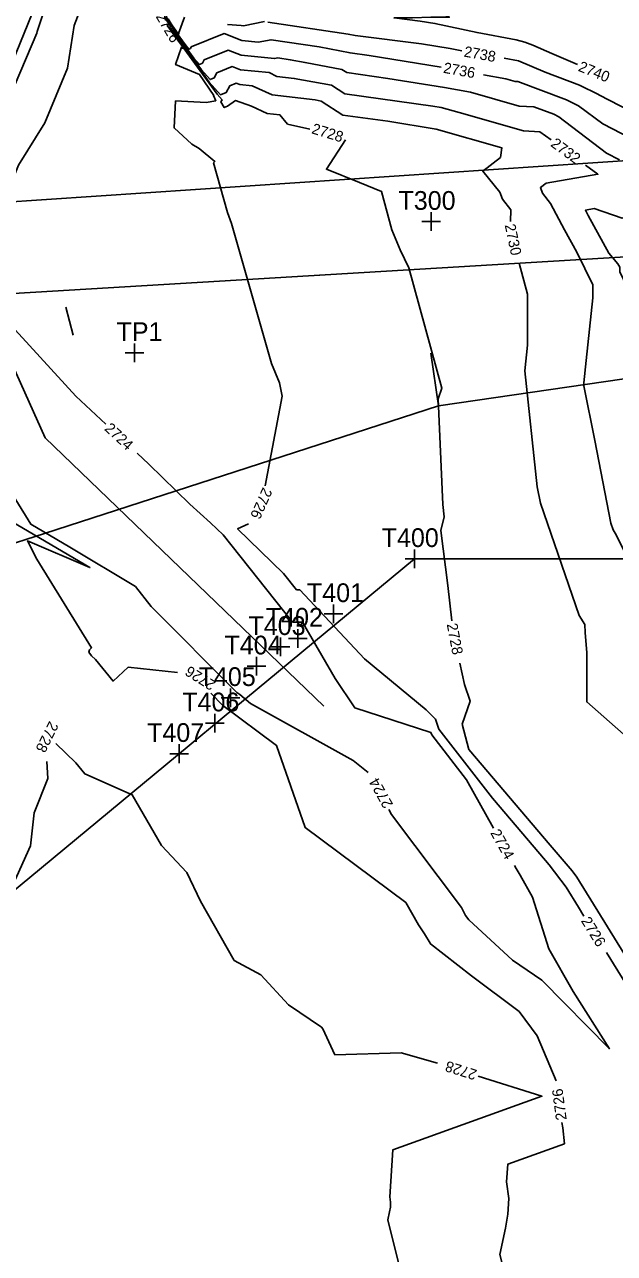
# Model space of a CAD drawing. Extents: x 1326424 to 1329294, y 1001359 to 1003823.
# Drawn here: x 1327879.6 to 1327989.8, y 1002856.6 to 1003086.3 of the extents above; entities that cross this region are included whole.
import ezdxf

# ---------------------------------------------------------------- set-up
doc = ezdxf.new("R2010")
doc.units = 0
for name, color, linetype in [('Default', 7, 'Continuous'), ('Prop Rem of Exist Asph Pvmt', 7, 'Continuous'), ('Prop SS Fill Line', 7, 'Continuous'), ('Prop SS Transition Line', 7, 'Continuous'), ('Scratch_Level_3', 7, 'Continuous')]:
    doc.layers.add(name, color=color, linetype=linetype)

msp = doc.modelspace()

# ---------------------------------------------------------------- linework, layer by layer
at = {"layer": 'Default'}
for p, q in [((1327659.26, 1003038.5), (1328184.23, 1003073.75)), ((1327956.95, 1003015.01), (1328177.22, 1003047.25)), ((1327956.95, 1003015.01), (1327955.51, 1003024.88)), ((1327883.39, 1002991.15), (1327956.95, 1003015.01)), ((1327655.18, 1002918.25), (1327883.39, 1002991.15))]:
    msp.add_line(p, q, dxfattribs=at)
msp.add_lwpolyline([(1327540.87, 1003325.42), (1327608.11, 1003285.07), (1327679.55, 1003254.32), (1327752.48, 1003225.71), (1327814.31, 1003211.74), (1327864.59, 1003173.14), (1327893.21, 1003143.63), (1327892.36, 1003116.11), (1327865.26, 1003049.62), (1327883.47, 1003009.08), (1327935.56, 1002958.9)], dxfattribs=at)
at = {"layer": 'Prop Rem of Exist Asph Pvmt'}
for p, q in [((1327955.6, 1003051.21), (1327955.6, 1003047.71)), ((1327957.35, 1003049.46), (1327953.85, 1003049.46)), ((1327901.93, 1003024.96), (1327898.43, 1003024.96)), ((1327900.18, 1003026.71), (1327900.18, 1003023.21)), ((1327952.45, 1002988.2), (1327952.45, 1002984.7)), ((1327954.2, 1002986.45), (1327950.7, 1002986.45)), ((1327937.36, 1002977.91), (1327937.36, 1002974.41)), ((1327939.11, 1002976.16), (1327935.61, 1002976.16)), ((1327930.68, 1002973.32), (1327930.68, 1002969.82)), ((1327929.2, 1002970.01), (1327925.7, 1002970.01)), ((1327927.45, 1002971.76), (1327927.45, 1002968.26)), ((1327932.43, 1002971.57), (1327928.93, 1002971.57)), ((1327922.96, 1002968.13), (1327922.96, 1002964.63)), ((1327924.71, 1002966.38), (1327921.21, 1002966.38)), ((1327918.13, 1002962.23), (1327918.13, 1002958.73)), ((1327919.88, 1002960.48), (1327916.38, 1002960.48)), ((1327915.16, 1002957.49), (1327915.16, 1002953.99)), ((1327916.91, 1002955.74), (1327913.41, 1002955.74)), ((1327908.5, 1002951.78), (1327908.5, 1002948.28)), ((1327910.25, 1002950.03), (1327906.75, 1002950.03))]:
    msp.add_line(p, q, dxfattribs=at)
msp.add_lwpolyline([(1327946.9, 1003116.73), (1327945.7, 1003116.52), (1327937.47, 1003113.03), (1327931.2, 1003110.86), (1327935.49, 1003103.61), (1327936.34, 1003101.4), (1327937.35, 1003100.59), (1327939.02, 1003099.75), (1327943.09, 1003097.24), (1327953.42, 1003090.51), (1327955.67, 1003089.46), (1327957.33, 1003088.47), (1327958.98, 1003087.65), (1327955.51, 1003087.68), (1327952.11, 1003087.53), (1327948.65, 1003087.52), (1327953.52, 1003086.91), (1327956.29, 1003086.49), (1327964.15, 1003084.78), (1327971.49, 1003083.44), (1327973.08, 1003082.98), (1327974.56, 1003082.42), (1327978.13, 1003080.88), (1327982.91, 1003078.81)], dxfattribs=at)
at = {"layer": 'Prop SS Fill Line'}
msp.add_line((1327888.69, 1003028.26), (1327887.37, 1003033.46), dxfattribs=at)
at = {"layer": 'Prop SS Transition Line'}
for p, q in [((1327872.68, 1003035.75), (1328093.84, 1003048.97)), ((1327952.45, 1002986.45), (1327671.95, 1002754.06)), ((1327952.45, 1002986.45), (1328127.23, 1002986.45))]:
    msp.add_line(p, q, dxfattribs=at)
at = {"layer": 'Scratch_Level_3'}
for points in [[(1327872.03, 1003054.66), (1327873.31, 1003056.72), (1327874.7, 1003061.52), (1327875.79, 1003070.18), (1327881.91, 1003084.69), (1327882, 1003084.98), (1327889.68, 1003108.17), (1327890.96, 1003110.45), (1327897.72, 1003115.14), (1327900.89, 1003116.1), (1327905.83, 1003122.65), (1327906.22, 1003122.81), (1327906.68, 1003123.95), (1327907.63, 1003126.35), (1327907.91, 1003126.8), (1327905.62, 1003133.94), (1327905.61, 1003133.92), (1327905.48, 1003134.05), (1327905.53, 1003134.2), (1327905.55, 1003134.27), (1327904.93, 1003141.71), (1327904.71, 1003142.53)], [(1327903.74, 1003105.84), (1327904.49, 1003098.43), (1327905.92, 1003087.36), (1327905.94, 1003087.15), (1327906.14, 1003087.27), (1327907.31, 1003085.59), (1327907.11, 1003085.49), (1327912.7, 1003077.79), (1327914.28, 1003076), (1327915.08, 1003076.3), (1327915.57, 1003077.27), (1327918.43, 1003078.42), (1327919.98, 1003077.82), (1327925.31, 1003077.29), (1327926.79, 1003076.6), (1327930, 1003076.23), (1327936.96, 1003074.94), (1327939.45, 1003073.33), (1327955.92, 1003071.04), (1327957.44, 1003070.79), (1327960.84, 1003069.82), (1327972.84, 1003066.43), (1327975.89, 1003066.26), (1327977.98, 1003064.73)], [(1327894.81, 1003011.63), (1327889.21, 1003016.82), (1327875.91, 1003031.42), (1327874.97, 1003032.48), (1327872.91, 1003044.87), (1327872.58, 1003046.12), (1327873.42, 1003047.47), (1327878.51, 1003060), (1327883.45, 1003067.91), (1327887.67, 1003078.16), (1327888.9, 1003086.12), (1327889.84, 1003088.51), (1327897.28, 1003092.76), (1327899.17, 1003094.59)], [(1327906.11, 1003087.74), (1327908.33, 1003084.57), (1327908.33, 1003084.57), (1327908.36, 1003084.53), (1327908.37, 1003084.52), (1327908.38, 1003084.52), (1327908.38, 1003084.52), (1327908.5, 1003084.57), (1327908.39, 1003084.58), (1327909.51, 1003087.66)], [(1327906.12, 1003087.58), (1327907.99, 1003084.91), (1327907.93, 1003084.88), (1327909.81, 1003082.28), (1327910.34, 1003081.68), (1327910.61, 1003081.78), (1327910.78, 1003082.11), (1327916.91, 1003084.58), (1327920.23, 1003083.29), (1327923.29, 1003082.99), (1327925.7, 1003083.44), (1327934.69, 1003082.09), (1327940.43, 1003080.97), (1327944.03, 1003080.52), (1327957.48, 1003078.33)], [(1327970.4, 1003049.46), (1327970.48, 1003051.64), (1327968.93, 1003053.65), (1327968.41, 1003054.99), (1327965.23, 1003058.87), (1327968.51, 1003061.44), (1327968.8, 1003063.22), (1327956.5, 1003066.76), (1327947.48, 1003068.2), (1327939.09, 1003069.36), (1327935.03, 1003071.99), (1327933.95, 1003072.19), (1327925.86, 1003073.14), (1327922.14, 1003074.86), (1327919.85, 1003075.09), (1327919.19, 1003075.35), (1327917.97, 1003074.85), (1327917.32, 1003073.56), (1327916.25, 1003073.16), (1327914.15, 1003075.54), (1327906.7, 1003085.79), (1327906.97, 1003085.94), (1327906.15, 1003087.11)], [(1327917.54, 1003086.28), (1327920.07, 1003086.08), (1327920.55, 1003086.07), (1327924.43, 1003086.82)], [(1327932.94, 1003066.76), (1327928.77, 1003067.69), (1327927.34, 1003069.39), (1327924.93, 1003069.67), (1327922, 1003071.02), (1327919.02, 1003072.08), (1327917.56, 1003071.03), (1327916.95, 1003070.77), (1327916.31, 1003071.86), (1327916.53, 1003072.23), (1327915.6, 1003073.3), (1327906.3, 1003086.1), (1327906.63, 1003086.28)], [(1327907.46, 1003085.53), (1327907.65, 1003085.25), (1327907.52, 1003085.18), (1327911.26, 1003080.03), (1327912.31, 1003078.84), (1327912.85, 1003079.04), (1327913.17, 1003079.69), (1327917.67, 1003081.5), (1327920.11, 1003080.56), (1327926.35, 1003079.93), (1327926.97, 1003080.05), (1327929.26, 1003079.7), (1327932.04, 1003079.16), (1327938.89, 1003077.9), (1327939.82, 1003077.3), (1327947.52, 1003076.23), (1327958.06, 1003074.51), (1327962.92, 1003073.62), (1327972.05, 1003071.05), (1327974.75, 1003070.9), (1327978.48, 1003069.51), (1327979.4, 1003069.05), (1327988.34, 1003062.27), (1327990.74, 1003061.03)], [(1327925.07, 1003086.74), (1327940.11, 1003084.48), (1327941.41, 1003084.23), (1327953.78, 1003082.66), (1327959.13, 1003081.79), (1327961.33, 1003081.38)], [(1327924.61, 1003000.1), (1327927.74, 1003016.81), (1327927.28, 1003019.31), (1327925.75, 1003022.96), (1327918.28, 1003049.09), (1327917.57, 1003051.17), (1327914.96, 1003060.41), (1327914.96, 1003060.42), (1327915.19, 1003060.68), (1327912.28, 1003063.12), (1327910.88, 1003063.91), (1327907.58, 1003066.96), (1327907.86, 1003072.02), (1327913.58, 1003071.72), (1327915.36, 1003072.03), (1327914.92, 1003073.01), (1327914.98, 1003073.04), (1327912.34, 1003076.95), (1327907.86, 1003078.79), (1327908.96, 1003082.04), (1327909.22, 1003081.82), (1327909.11, 1003081.98)], [(1327969.21, 1003079.98), (1327971.91, 1003079.51), (1327976.86, 1003077.36), (1327983.29, 1003074.96), (1327986.85, 1003073.18), (1327986.91, 1003073.14), (1327994.85, 1003069.03), (1328002.41, 1003065.69), (1328002.85, 1003065.46), (1328007.58, 1003061.78), (1328009.45, 1003060.7), (1328012.79, 1003055.13), (1328013.44, 1003052.28), (1328011.82, 1003048.92), (1328014.98, 1003043.43), (1328015.39, 1003042.24), (1328016.41, 1003039.34), (1328016.82, 1003032.84), (1328017.47, 1003028.52), (1328021.8, 1003024.04), (1328023.35, 1003019.89), (1328023.75, 1003018.89), (1328023.96, 1003017.92), (1328025.74, 1003010.47)], [(1327965.35, 1003076.91), (1327969.56, 1003076.15), (1327971.26, 1003075.67), (1327971.76, 1003075.64), (1327980.88, 1003072.24), (1327983.12, 1003071.12), (1327987.62, 1003067.7), (1327992.79, 1003065.03)], [(1327959.45, 1002974.83), (1327958.7, 1002981.48), (1327957.39, 1002991.72), (1327958.01, 1002994.28), (1327957.75, 1002996.57), (1327956.9, 1003016.33), (1327957.55, 1003018.36), (1327951.4, 1003040.82), (1327949.77, 1003044.17), (1327948.25, 1003047.9), (1327946.33, 1003055.07), (1327942.21, 1003056.76), (1327936.02, 1003059.24), (1327939.59, 1003064.74)], [(1327984.43, 1003060), (1327986.73, 1003058.31), (1327977.06, 1003056.67), (1327976, 1003055.81), (1327976.41, 1003054.76), (1327977.9, 1003052.82), (1327980.47, 1003047.92), (1327982.77, 1003043.72), (1327985.79, 1003037.65), (1327985.8, 1003035.2), (1327984.56, 1003023.48), (1327984.13, 1003019.31), (1327984.11, 1003018.8), (1327986.14, 1003008.53), (1327989.13, 1002993.1), (1327989.55, 1002991.88), (1327990.12, 1002990.95), (1327996.72, 1002977.61), (1327996.99, 1002974.71)], [(1327999.44, 1003053.57), (1327998.18, 1003052.48), (1327994.92, 1003051.41), (1327991.28, 1003050.12), (1327986, 1003051.89), (1327984.39, 1003051.59), (1327984.9, 1003050.61), (1327988.76, 1003043.56), (1327990.45, 1003041.56), (1327990.85, 1003040.93), (1327990.83, 1003040.65), (1327990.81, 1003040.09), (1327996.34, 1003028.48), (1327996.51, 1003028.08), (1327996.49, 1003027.54), (1327996.13, 1003015.68), (1327998.05, 1003005.97), (1328002.23, 1002993.67), (1328006.14, 1002984.71), (1328007.49, 1002981.22), (1328006.62, 1002978.52), (1328006.56, 1002972.98)], [(1327995.93, 1002948.64), (1327995.77, 1002949.92), (1327984.66, 1002959.69), (1327984.64, 1002968.89), (1327984.37, 1002972.67), (1327984.29, 1002974.15), (1327983.22, 1002975.88), (1327975.98, 1002996.85), (1327975.39, 1002999.89), (1327973.09, 1003021.56), (1327973.6, 1003026.37), (1327973.56, 1003035.87), (1327972.04, 1003041.68)], [(1327865.33, 1003016.43), (1327870.35, 1003004.9), (1327875.32, 1002996.87), (1327875.89, 1002995.63), (1327877.3, 1002993.37), (1327891.84, 1002984.8), (1327880.18, 1002989.8), (1327881.92, 1002986.35), (1327892.15, 1002969.82), (1327891.8, 1002969.41), (1327891.67, 1002969.02), (1327892.17, 1002968.34), (1327892.88, 1002967.65), (1327896.16, 1002963.59), (1327898.98, 1002966.18), (1327908.18, 1002965.22)], [(1327869.78, 1003010.83), (1327877.82, 1002997.84), (1327878, 1002997.46), (1327880.84, 1002992.9), (1327888.07, 1002988.63), (1327900.35, 1002981.26), (1327903.3, 1002977.55), (1327919.29, 1002961.48), (1327919.83, 1002961.08), (1327921.87, 1002959.44), (1327940.99, 1002948.74), (1327943.82, 1002946.51)], [(1327967.25, 1002936.1), (1327962.2, 1002945.14), (1327955.68, 1002953.54), (1327955.54, 1002953.96), (1327941.31, 1002958.6), (1327937.67, 1002964.11), (1327931.58, 1002974.59), (1327929.69, 1002974.62), (1327916.71, 1002990.92), (1327914.39, 1002993.16), (1327910.53, 1002996.68), (1327902.88, 1003004.14), (1327900.67, 1003006.19)], [(1327984.13, 1002919.68), (1327983.09, 1002921.37), (1327980.82, 1002925.06), (1327977.65, 1002929.25), (1327975.88, 1002931.33), (1327967.06, 1002941.7), (1327957.02, 1002954.64), (1327956.42, 1002956.46), (1327954.65, 1002958.2), (1327943.15, 1002967.75), (1327931.03, 1002980.63), (1327930.46, 1002980.64), (1327928.01, 1002983.72), (1327919.43, 1002992.03), (1327921.44, 1002992.99)], [(1328012.94, 1002885.08), (1328009.49, 1002890), (1328007.66, 1002891.96), (1328005.18, 1002894.39), (1327999.74, 1002902.56), (1327996.88, 1002905.46), (1327995.57, 1002906.25), (1327988.51, 1002917.69), (1327982.81, 1002926.95), (1327981.92, 1002928.13), (1327977.83, 1002932.94), (1327962.63, 1002950.82), (1327961.36, 1002955.57), (1327962.87, 1002959.82), (1327961.79, 1002962.98), (1327960.95, 1002966.97)], [(1327914.45, 1002961.32), (1327916.7, 1002959.06), (1327926.69, 1002951.57), (1327932.04, 1002936.23), (1327950.83, 1002922.22), (1327953.22, 1002918.05), (1327954.33, 1002916.38), (1327955.38, 1002914.63), (1327955.48, 1002914.47), (1327963.09, 1002908.55), (1327972, 1002901.88), (1327975.36, 1002897.3), (1327978.96, 1002888.89)], [(1327885.48, 1002951.94), (1327889.22, 1002948.3), (1327890.87, 1002946.25), (1327899.75, 1002942.34), (1327905.2, 1002932.85), (1327909.94, 1002927.85), (1327912.51, 1002922.48), (1327918.77, 1002911.41), (1327923.77, 1002908.69), (1327928.93, 1002903.11), (1327935.09, 1002898.91), (1327935.38, 1002898.59), (1327937.6, 1002893.76), (1327950.01, 1002894.16), (1327956.76, 1002892.19)], [(1327852.03, 1002856.8), (1327853.21, 1002857.69), (1327861.04, 1002868.08), (1327860.25, 1002882.26), (1327862.33, 1002893.08), (1327864.65, 1002901.25), (1327873.04, 1002915.81), (1327880.74, 1002932.79), (1327881.41, 1002938.96), (1327884.01, 1002945.41), (1327883.82, 1002948.59)], [(1327947.69, 1002939.6), (1327948.16, 1002938.64), (1327961.24, 1002921.3), (1327962.01, 1002919.82), (1327962.64, 1002918.96), (1327970.79, 1002911.44), (1327976.23, 1002907.68), (1327988.89, 1002894.88), (1327982.09, 1002905.62), (1327977.55, 1002913.54), (1327974.49, 1002923.22), (1327972.18, 1002927.34), (1327971.44, 1002928.58), (1327971.14, 1002929.11)], [(1327994.66, 1002902.63), (1327988.34, 1002912.87)], [(1327964.39, 1002889.79), (1327976.27, 1002886.01), (1327948.4, 1002875.99), (1327947.88, 1002867.23), (1327948.01, 1002866.24), (1327947.96, 1002865.29), (1327947.81, 1002864.45), (1327947.48, 1002862.9), (1327952.1, 1002844.34), (1327951.84, 1002843.07), (1327950.45, 1002840.62), (1327949.87, 1002840.03), (1327949.39, 1002839.25), (1327953.18, 1002826.51), (1327953.15, 1002825.3), (1327953.04, 1002823.91), (1327953.06, 1002822.83), (1327952.18, 1002820.17)], [(1327980.01, 1002881.13), (1327980.19, 1002880.1), (1327980.48, 1002877.13), (1327969.88, 1002873.32), (1327969.68, 1002870.03), (1327970.08, 1002866.94), (1327969.92, 1002863.97), (1327969.46, 1002861.34), (1327968.43, 1002856.47), (1327970.16, 1002849.51), (1327969.48, 1002846.31), (1327965.99, 1002840.11), (1327964.52, 1002838.61), (1327963.3, 1002836.63), (1327964.72, 1002831.85), (1327964.65, 1002829.11), (1327964.4, 1002825.94), (1327964.45, 1002823.48), (1327962.06, 1002816.28), (1327960.92, 1002812.86), (1327960.74, 1002809.43), (1327957.82, 1002795.9), (1327958.35, 1002792.72), (1327958.11, 1002792.14)]]:
    msp.add_lwpolyline(points, dxfattribs=at)

# ---------------------------------------------------------------- texts
at = {"layer": 'Prop Rem of Exist Asph Pvmt'}
msp.add_text('2740', height=2, rotation=337.9924, dxfattribs=at).set_placement((1327982.9, 1003077.67))
at = {"layer": 'Scratch_Level_3'}
for s, rotation, p in [('2726', 300.4446, (1327904.08, 1003087.8)), ('2738', 349.8923, (1327961.6, 1003080.31)), ('2736', 349.8068, (1327957.75, 1003077.28)), ('2728', 343.0624, (1327933.12, 1003065.98)), ('2732', 323.7324, (1327977.75, 1003063.66)), ('2730', 281.9074, (1327969.31, 1003048.81)), ('2724', 317.1527, (1327894.43, 1003010.61)), ('2726', 245.9887, (1327924.17, 1002999.92)), ('2728', 280.8406, (1327958.48, 1002974.22)), ('2726', 148.1108, (1327915.53, 1002963.41)), ('2728', 243.6014, (1327884.29, 1002956.24)), ('2724', 119.1823, (1327948.53, 1002940.55)), ('2724', 299.1608, (1327966.58, 1002935.24)), ('2726', 301.7016, (1327983.5, 1002918.8)), ('2728', 162.5221, (1327964.29, 1002890.88)), ('2726', 97.696, (1327980.91, 1002881.66))]:
    msp.add_text(s, height=2, rotation=rotation, dxfattribs=at).set_placement(p)
for s, p in [('T300', (1327949.48, 1003051.66)), ('TP1', (1327896.82, 1003027.16)), ('T400', (1327946.34, 1002988.65)), ('T401', (1327932.38, 1002978.36)), ('T402', (1327924.7, 1002973.77)), ('T403', (1327921.47, 1002972.21)), ('T404', (1327916.98, 1002968.58)), ('T405', (1327912.15, 1002962.68)), ('T406', (1327909.1, 1002957.94)), ('T407', (1327902.52, 1002952.23))]:
    msp.add_text(s, height=3.5, dxfattribs=at).set_placement(p)

doc.saveas('drawing.dxf')
